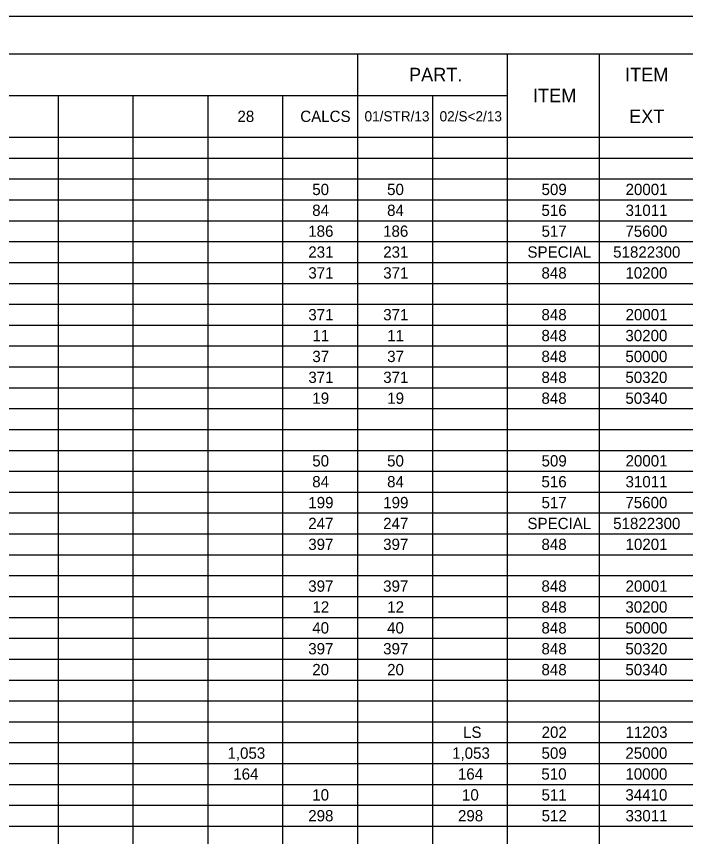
# Model space of a CAD drawing. Extents: x -53.2 to 35.8, y -26.4 to 35.9.
# Drawn here: x 8.98 to 17.96, y 11 to 22 of the extents above; entities that cross this region are included whole.
import ezdxf

# ---------------------------------------------------------------- set-up
doc = ezdxf.new("R2010")
doc.units = 0
for name, color, linetype in [('Default', 7, 'Continuous'), ('SH_Border', 7, 'Continuous'), ('SH_Cut_Line', 7, 'Continuous')]:
    doc.layers.add(name, color=color, linetype=linetype)

msp = doc.modelspace()

# ---------------------------------------------------------------- linework, layer by layer
at = {"layer": 'Default'}
for p, q in [((1.5, 21.5), (32, 21.5)), ((13.555, 21.5), (13.555, 0.5)), ((15.564, 21.5), (15.564, 0.5)), ((16.799, 21.5), (16.799, 0.5)), ((1.5, 20.94), (15.564, 20.94)), ((9.537, 20.94), (9.537, 0.5)), ((10.541, 20.94), (10.541, 0.5)), ((11.546, 20.94), (11.546, 0.5)), ((12.55, 20.94), (12.55, 0.5)), ((14.56, 20.94), (14.56, 0.5)), ((1.5, 20.38), (32, 20.38)), ((1.5, 20.1), (32, 20.1)), ((1.5, 19.82), (32, 19.82)), ((1.5, 19.54), (32, 19.54)), ((1.5, 19.26), (32, 19.26)), ((1.5, 18.98), (32, 18.98)), ((1.5, 18.7), (32, 18.7)), ((1.5, 18.42), (32, 18.42)), ((1.5, 18.14), (32, 18.14)), ((1.5, 17.86), (32, 17.86)), ((1.5, 17.58), (32, 17.58)), ((1.5, 17.3), (32, 17.3)), ((1.5, 17.02), (32, 17.02)), ((1.5, 16.74), (32, 16.74)), ((1.5, 16.46), (32, 16.46)), ((1.5, 16.18), (32, 16.18)), ((1.5, 15.9), (32, 15.9)), ((1.5, 15.62), (32, 15.62)), ((1.5, 15.34), (32, 15.34)), ((1.5, 15.06), (32, 15.06)), ((1.5, 14.78), (32, 14.78)), ((1.5, 14.5), (32, 14.5)), ((1.5, 14.22), (32, 14.22)), ((1.5, 13.94), (32, 13.94)), ((1.5, 13.66), (32, 13.66)), ((1.5, 13.38), (32, 13.38)), ((1.5, 13.1), (32, 13.1)), ((1.5, 12.82), (32, 12.82)), ((1.5, 12.54), (32, 12.54)), ((1.5, 12.26), (32, 12.26)), ((1.5, 11.98), (32, 11.98)), ((1.5, 11.7), (32, 11.7)), ((1.5, 11.42), (32, 11.42)), ((1.5, 11.14), (32, 11.14))]:
    msp.add_line(p, q, dxfattribs=at)
at = {"layer": 'SH_Border'}
msp.add_lwpolyline([(1.5, 21.5), (33.5, 21.5), (33.5, 0.5), (1.5, 0.5)], close=True, dxfattribs=at)
at = {"layer": 'SH_Cut_Line'}
msp.add_lwpolyline([(0, 0), (34, 0), (34, 22), (0, 22)], close=True, dxfattribs=at)

# ---------------------------------------------------------------- texts
at = {"layer": 'Default'}
for s, height, p in [('PART.', 0.1818, (14.246, 21.129)), ('ITEM', 0.1818, (17.145, 21.129)), ('ITEM', 0.1818, (15.91, 20.849)), ('28', 0.1515, (11.944, 20.584)), ('CALCS', 0.1515, (12.787, 20.584)), ('01/STR/13', 0.1364, (13.649, 20.592)), ('02/S<2/13', 0.1364, (14.656, 20.592)), ('EXT', 0.1818, (17.199, 20.569)), ('50', 0.1515, (12.948, 19.604)), ('50', 0.1515, (13.952, 19.604)), ('509', 0.1515, (16.024, 19.604)), ('20001', 0.1515, (17.151, 19.604)), ('84', 0.1515, (12.947, 19.324)), ('84', 0.1515, (13.952, 19.324)), ('516', 0.1515, (16.023, 19.324)), ('31011', 0.1515, (17.151, 19.324)), ('186', 0.1515, (12.894, 19.044)), ('186', 0.1515, (13.898, 19.044)), ('517', 0.1515, (16.024, 19.044)), ('75600', 0.1515, (17.149, 19.044)), ('231', 0.1515, (12.895, 18.764)), ('231', 0.1515, (13.9, 18.764)), ('SPECIAL', 0.1515, (15.835, 18.764)), ('51822300', 0.1515, (16.985, 18.764)), ('371', 0.1515, (12.895, 18.484)), ('371', 0.1515, (13.9, 18.484)), ('848', 0.1515, (16.023, 18.484)), ('10200', 0.1515, (17.149, 18.484)), ('371', 0.1515, (12.895, 17.924)), ('371', 0.1515, (13.9, 17.924)), ('848', 0.1515, (16.023, 17.924)), ('20001', 0.1515, (17.151, 17.924)), ('11', 0.1515, (12.95, 17.644)), ('11', 0.1515, (13.954, 17.644)), ('848', 0.1515, (16.023, 17.644)), ('30200', 0.1515, (17.149, 17.644)), ('37', 0.1515, (12.949, 17.364)), ('37', 0.1515, (13.953, 17.364)), ('848', 0.1515, (16.023, 17.364)), ('50000', 0.1515, (17.149, 17.364)), ('371', 0.1515, (12.895, 17.084)), ('371', 0.1515, (13.9, 17.084)), ('848', 0.1515, (16.023, 17.084)), ('50320', 0.1515, (17.149, 17.084)), ('19', 0.1515, (12.949, 16.804)), ('19', 0.1515, (13.954, 16.804)), ('848', 0.1515, (16.023, 16.804)), ('50340', 0.1515, (17.149, 16.804)), ('50', 0.1515, (12.948, 15.964)), ('50', 0.1515, (13.952, 15.964)), ('509', 0.1515, (16.024, 15.964)), ('20001', 0.1515, (17.151, 15.964)), ('84', 0.1515, (12.947, 15.684)), ('84', 0.1515, (13.952, 15.684)), ('516', 0.1515, (16.023, 15.684)), ('31011', 0.1515, (17.151, 15.684)), ('199', 0.1515, (12.895, 15.404)), ('199', 0.1515, (13.9, 15.404)), ('517', 0.1515, (16.024, 15.404)), ('75600', 0.1515, (17.149, 15.404)), ('247', 0.1515, (12.894, 15.124)), ('247', 0.1515, (13.899, 15.124)), ('SPECIAL', 0.1515, (15.835, 15.124)), ('51822300', 0.1515, (16.985, 15.124)), ('397', 0.1515, (12.894, 14.844)), ('397', 0.1515, (13.899, 14.844)), ('848', 0.1515, (16.023, 14.844)), ('10201', 0.1515, (17.151, 14.844)), ('397', 0.1515, (12.894, 14.284)), ('397', 0.1515, (13.899, 14.284)), ('848', 0.1515, (16.023, 14.284)), ('20001', 0.1515, (17.151, 14.284)), ('12', 0.1515, (12.95, 14.004)), ('12', 0.1515, (13.954, 14.004)), ('848', 0.1515, (16.023, 14.004)), ('30200', 0.1515, (17.149, 14.004)), ('40', 0.1515, (12.948, 13.724)), ('40', 0.1515, (13.952, 13.724)), ('848', 0.1515, (16.023, 13.724)), ('50000', 0.1515, (17.149, 13.724)), ('397', 0.1515, (12.894, 13.444)), ('397', 0.1515, (13.899, 13.444)), ('848', 0.1515, (16.023, 13.444)), ('50320', 0.1515, (17.149, 13.444)), ('20', 0.1515, (12.948, 13.164)), ('20', 0.1515, (13.952, 13.164)), ('848', 0.1515, (16.023, 13.164)), ('50340', 0.1515, (17.149, 13.164)), ('LS', 0.1515, (14.971, 12.324)), ('202', 0.1515, (16.025, 12.324)), ('11203', 0.1515, (17.151, 12.324)), ('1,053', 0.1515, (11.81, 12.044)), ('1,053', 0.1515, (14.824, 12.044)), ('509', 0.1515, (16.024, 12.044)), ('25000', 0.1515, (17.149, 12.044)), ('164', 0.1515, (11.888, 11.764)), ('164', 0.1515, (14.902, 11.764)), ('510', 0.1515, (16.022, 11.764)), ('10000', 0.1515, (17.149, 11.764)), ('10', 0.1515, (12.948, 11.484)), ('10', 0.1515, (14.957, 11.484)), ('511', 0.1515, (16.024, 11.484)), ('34410', 0.1515, (17.149, 11.484)), ('298', 0.1515, (12.894, 11.204)), ('298', 0.1515, (14.903, 11.204)), ('512', 0.1515, (16.025, 11.204)), ('33011', 0.1515, (17.151, 11.204))]:
    msp.add_text(s, height=height, dxfattribs=at).set_placement(p)

doc.saveas('drawing.dxf')
